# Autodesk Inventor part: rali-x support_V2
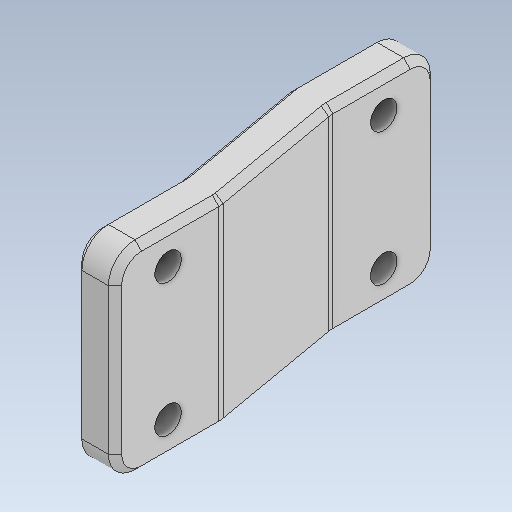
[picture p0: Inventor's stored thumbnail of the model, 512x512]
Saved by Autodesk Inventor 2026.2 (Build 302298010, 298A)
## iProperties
Created: 2026-04
Part Number: rali-x support_V2
Material: 일반
Document SubType Name: Modeling
Designer: khw
Density: 1 g/cm^3
Appearance: 기본값
Author: khw
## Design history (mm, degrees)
sketch "스케치1"
  geometry: L1 (0, 0)-(0, -16); L2 (0, -16)-(3.5, -36); L3 (3.5, -52)-(9.5, -52); L4 (9.5, -52)-(9.5, -36); L5 (9.5, -36)-(6, -16); L6 (6, -16)-(6, 0); L7 (6, 0)-(0, 0); L8 (0, -16)-(6, -16); L9 (3.5, -36)-(9.5, -36); L10 (3.5, -36)-(3.5, -52); 2 further points
  constraints: 20 end point, 4 parallel, 2 midpoint, 2 perpendicular, 1 vertical
  dimensions: "d0" = 6 distance from line of L6 point (0, -8); "d2" = 20 vertical distance of L1.end L2.end; "d3" = 6 distance from line of point (9.5, -44) L10; "d4" = 3.5 horizontal distance of L2.end L1.end; "d5" = 16 distance between parallel lines of L8 L7; "d6" = 16 distance of L3.end L4.end
extrude "돌출1" new body sketch "스케치1" distance "d7" = 30; taper "d8" = 0 deg
sketch "스케치2"
  geometry: L1 (0, 0)-(16, 0) reference; L2 (16, 0)-(16, 30) reference; L3 (0, 30)-(16, 30) reference; L4 (0, 0)-(0, 30) reference; L5 (-36, 0)-(-20, 0) reference; L6 (-20, 0)-(-20, 30) reference; L7 (-36, 30)-(-20, 30) reference; L8 (-36, 0)-(-36, 30) reference; L9 (-28, 0)-(-28, 30); L10 (8, 0)-(8, 30); L11 (16, 15)-(-36, 15); L12 (0, 0)-(-20, 0) reference; L13 (-20, 0)-(-20, 30) reference; L14 (0, 30)-(-20, 30) reference; L15 (0, 0)-(0, 30) reference; L16 (-17, 3)-(-3, 3); L17 (-3, 3)-(-3, 27); L18 (-3, 27)-(-17, 27); L19 (-17, 27)-(-17, 3); L20 (-3, 23.031)-(-14.685, 3); L21 (-17, 6.969)-(-5.315, 27); L22 (-14.685, 27)-(-3, 6.969); L23 (-5.315, 3)-(-17, 23.031); L24 (-17, 17)-(-3, 17); L25 (-3, 13)-(-7.048, 13); L26 (-7.048, 13)-(-17, 13); L27 (-3, 27)-(-17, 3); L28 (-3, 3)-(-17, 27); C1 r 2 at (8, 5); C2 r 2 at (-28, 5); C3 r 2 at (-28, 25); C4 r 2 at (8, 25); 8 further points
  constraints: 32 end point, 17 point on line, 7 midpoint, 4 centre point, 4 parallel, 2 perpendicular, 2 symmetric about line, 5 other
  dimensions: "d9" = 4 diameter of C1; "d10" = 10 distance from line of L11 C1.centre; "d11" = 4 diameter of C2; "d12" = 10 distance from line of L11 C2.centre; "d13" = 4 distance between parallel lines of L23 L22; "d15" = 4 distance between parallel lines of L25 L24; "d16" = 4 distance between parallel lines of L21 L20; "d17" = 2 distance between parallel lines of L21 L27; "d18" = 3 distance from line of L14 point (-10, 27); "d19" = 2 distance between parallel lines of L23 L28; "d20" = 2 distance between parallel lines of L11 L26
extrude "돌출2" cut sketch "스케치2" extent not by distance; stored distance "d21" = 0; taper "d22" = 0 deg
fillet "모깎기1" dims "d23" = 4
chamfer "모따기1" distance "d24" = 1; stored, may be unused: second distance "d25" = 2, angle "d26" = 45 deg
node "솔리드1"
node "투영된 루프1"
node "투영된 루프2"
node "투영된 루프3"
